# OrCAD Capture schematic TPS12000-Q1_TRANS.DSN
size C
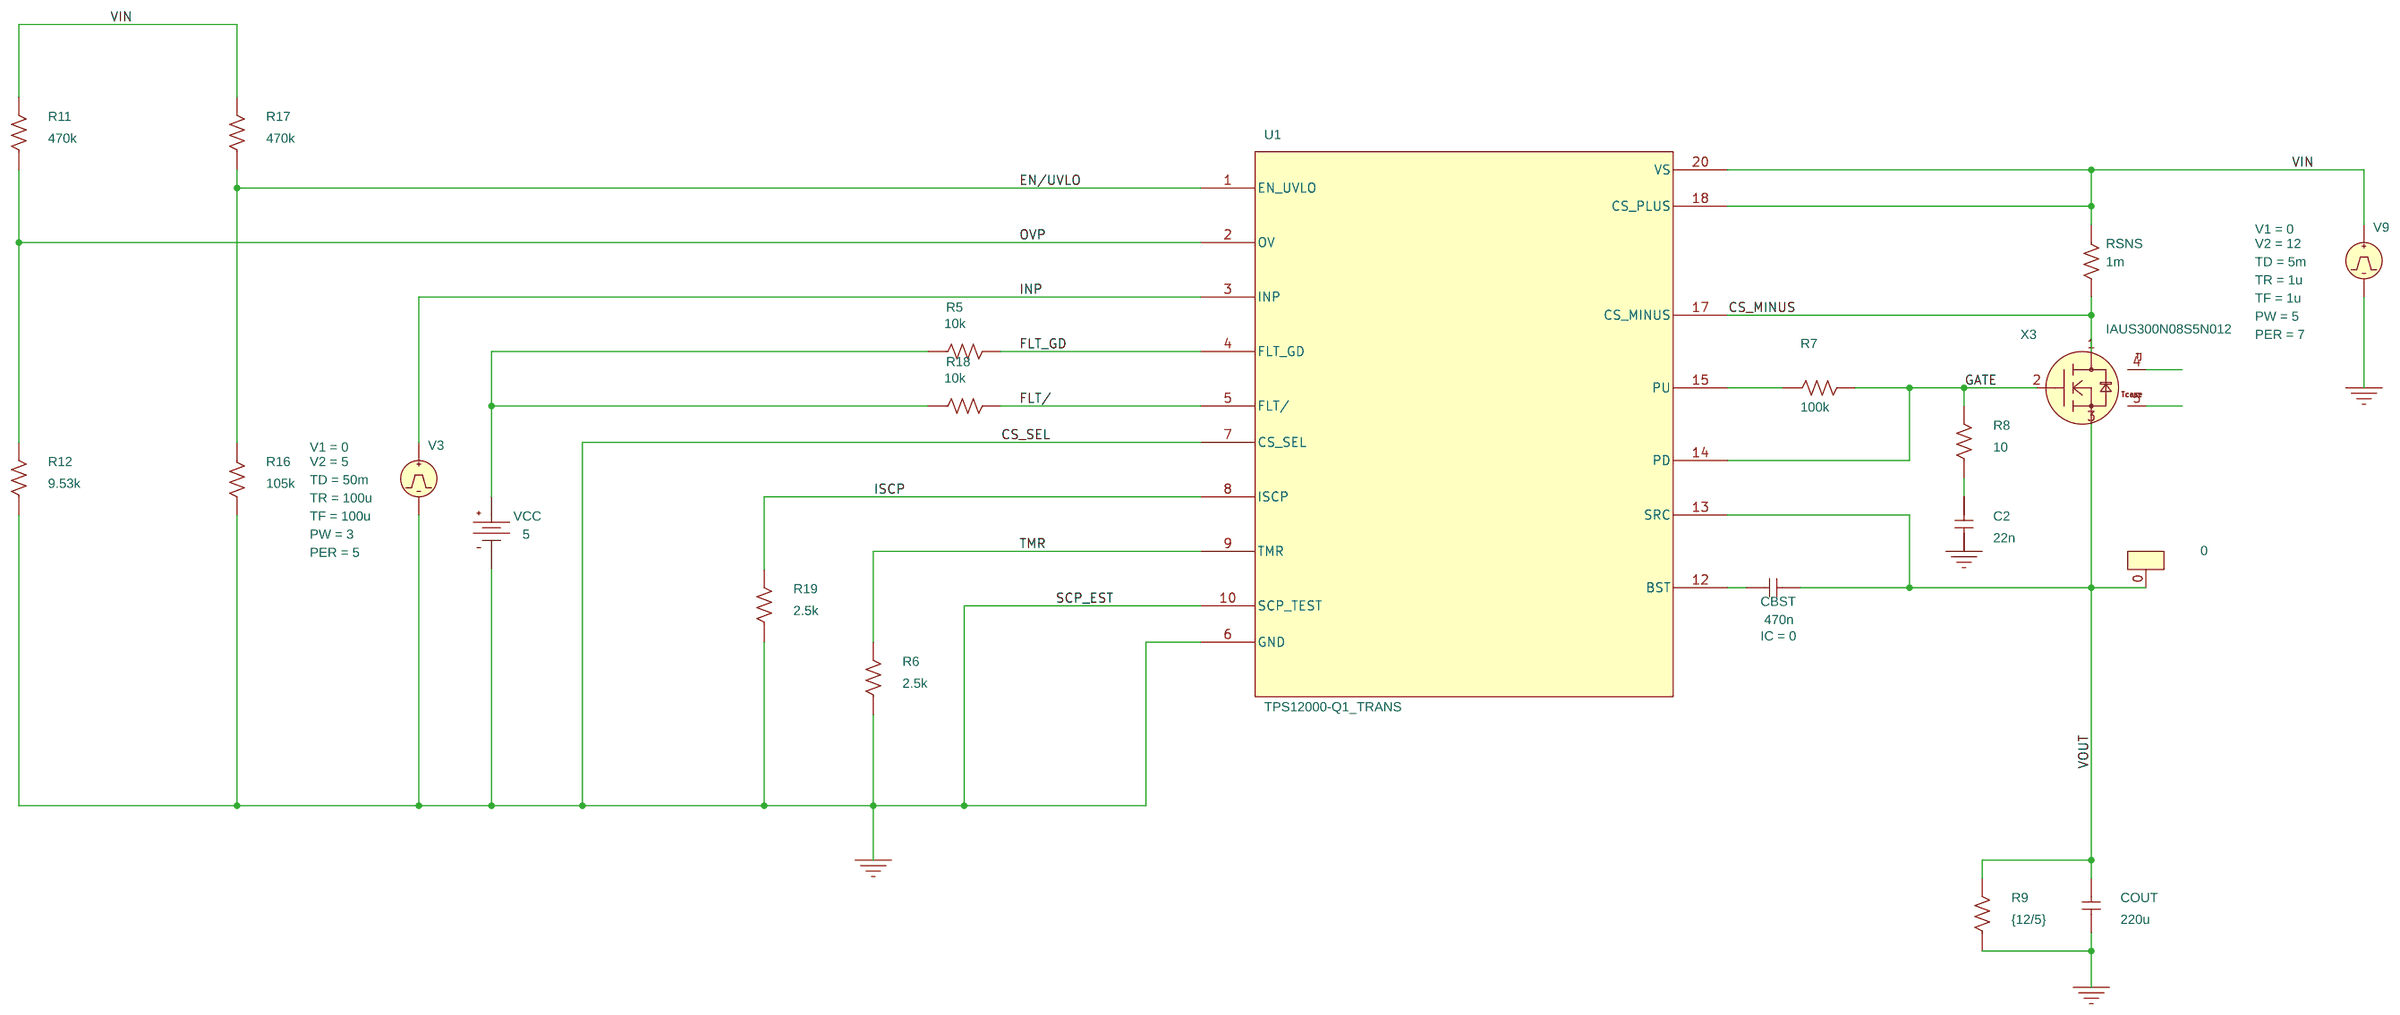
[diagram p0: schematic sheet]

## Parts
C2  22n  [RAD/CK05]
CBST  470n  [RAD/CK05]
COUT  220u  [RAD/CK05]
IC1  0
R5  10k  [AX/RC05]
R6  2.5k  [AX/RC05]
R7  100k  [AX/RC05]
R8  10  [AX/RC05]
R9  {12/5}  [AX/RC05]
R11  470k  [AX/RC05]
R12  9.53k  [AX/RC05]
R16  105k  [AX/RC05]
R17  470k  [AX/RC05]
R18  10k  [AX/RC05]
R19  2.5k  [AX/RC05]
RSNS  1m  [AX/RC05]
U1  TPS12000-Q1_TRANS
V3  VPULSE
V9  VPULSE
VCC  VDC
X3  IAUS300N08S5N012

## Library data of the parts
C2 COUT = C
CBST = C: IC: 0
IC1 = IC1
R5-R9 R11 R12 R16-R19 RSNS = R
U1 = TPS12000-Q1_TRANS
V3 = VPULSE: PER: 5; PW: 3; TD: 50m; TF: 100u; TR: 100u; V1: 0; V2: 5
V9 = VPULSE: PER: 7; PW: 5; TD: 5m; TF: 1u; TR: 1u; V1: 0; V2: 12
VCC = VDC: DC: 5
X3 = IAUS300N08S5N012

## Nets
VIN: R11.2 R17.2 RSNS.1 U1.18(CS_PLUS) U1.20(VS) V9.1(+)
0: C2.1 COUT.1 R6.1 R9.1 R12.1 R16.2 R19.1 U1.6(GND) U1.7(CS_SEL) U1.10(SCP_TEST) V3.2(-) V9.2(-) VCC.1(-)
CS_MINUS: RSNS.2 U1.17(CS_MINUS) X3.1(drain)
EN/UVLO: R16.1 R17.1 U1.1(EN_UVLO)
FLT/: R18.2 U1.5(FLT/)
FLT_GD: R5.2 U1.4(FLT_GD)
GATE: R7.2 R8.2 U1.14(PD) X3.2(gate)
INP: U1.3(INP) V3.1(+)
ISCP: R19.2 U1.8(ISCP)
OVP: R11.1 R12.2 U1.2(OV)
TMR: R6.2 U1.9(TMR)
VOUT: CBST.2 COUT.2 IC1.0(+) R9.2 U1.13(SRC) X3.3(source)
N16718757: R5.1 R18.1 VCC.0(+)
N16718877: R7.1 U1.15(PU)
N16719063: C2.2 R8.1
N16720069: CBST.1 U1.12(BST)

Not connected (* = marked no-connect by the designer): X3 4(Tj) 5(Tcase)
